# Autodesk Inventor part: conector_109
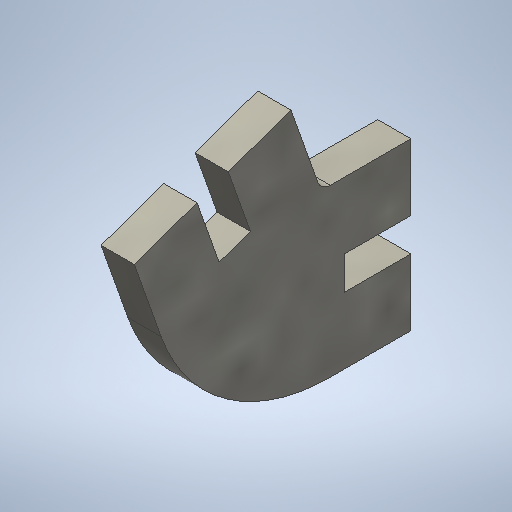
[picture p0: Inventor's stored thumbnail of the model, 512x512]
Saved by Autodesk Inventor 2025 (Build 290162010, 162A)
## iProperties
Created: 2025-02
Part Number: conector_109
Material: Paper
Document SubType Name: Modeling
Designer: BennF
Density: 0.93 g/cm^3
Appearance: Cardboard - Chipboard
Author: BennF
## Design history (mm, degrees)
sketch "Sketch2"
  geometry: L1 (0, -1)-(6.061, -1); L2 (6.061, -1)-(6.061, -6); L3 (6.061, -6)-(1.061, -6); L4 (1.061, -6)-(1.061, -8.5); L5 (1.061, -8.5)-(6.061, -8.5); L6 (6.061, -8.5)-(6.061, -13.5); L7 (6.061, -13.5)-(0, -13.5); L8 (-0.943, -0.333)-(-2.963, 5.381); L9 (-2.963, 5.381)-(-7.677, 3.714); L10 (-7.677, 3.714)-(-6.01, -1); L11 (-6.01, -1)-(-8.367, -1.833); L12 (-8.367, -1.833)-(-10.034, 2.881); L13 (-10.034, 2.881)-(-14.748, 1.214); L14 (-14.748, 1.214)-(-12.728, -4.5); L15 (-6.01, -1)-(1.061, -6); A1 r 1 centre (0, 0) between (-0.943, -0.333) and (0, -1); A2 r 13.5 centre (0, 0) between (-12.728, -4.5) and (0, -13.5); 1 further point
  constraints: 30 end point, 10 perpendicular, 5 equal length, 4 point on circle, 4 point on line, 4 tangent, 2 centre point, 2 coincident, 1 horizontal
  dimensions: "d0" = 2.5 distance of L3.end L4.end (= thickness); "d1" = 5 distance of L2.end L3.end (= slot_depth); "d2" = 5 distance of L1.end L2.end (= slot_dis_1); "d3" = 1 radius of A1; "d4" = 109.471 deg angle of L1 L8 (= con_angle_4); "d8" = 5 vertical distance of L3.end L10.end (computed from slot_clearenece)
extrude "Extrusion1" new body sketch "Sketch2" distance "d6" = 2.5 (= thickness); taper "d7" = 0 deg
sketch "laser"
  geometry: L1 (-3.714, -7.677)-(1, -6.01) reference; L2 (1, -6.01)-(1.833, -8.367) reference; L3 (1.833, -8.367)-(-2.881, -10.034) reference; L4 (-2.881, -10.034)-(-1.214, -14.748) reference; L5 (-1.214, -14.748)-(4.5, -12.728) reference; L6 (13.5, 0)-(13.5, 6.061) reference; L7 (13.5, 6.061)-(8.5, 6.061) reference; L8 (8.5, 6.061)-(8.5, 1.061) reference; L9 (8.5, 1.061)-(6, 1.061) reference; L10 (6, 1.061)-(6, 6.061) reference; L11 (6, 6.061)-(1, 6.061) reference; L12 (1, 6.061)-(1, 0) reference; L13 (0.333, -0.943)-(-5.381, -2.963) reference; L14 (-5.381, -2.963)-(-3.714, -7.677) reference; A1 r 13.5 centre (0, 0) between (4.5, -12.728) and (13.5, 0) reference; A2 r 1 centre (0, 0) between (0.333, -0.943) and (1, 0) reference; 1 further point
  node "Projected Loop1"
body "Solid1"
other parameters: "thickness" = 2.5 [user parameter; used in 2 equation terms], "clearence" = -0.5 [user parameter], "slot_depth" = 5 [user parameter; used in 1 equation term], "slot_dis_1" = 5 [user parameter; used in 1 equation term], "slot_dis_2" = 12 [user parameter], "slot_clearenece" = 3 [user parameter; used in 1 equation term], "con_angle_1" = 20.34444 [user parameter], "con_angle_2" = 60 deg [user parameter], "con_angle_3" = 12.30959 [user parameter], "con_angle_4" = 109.471 deg [user parameter; used in 1 equation term], "con_angle_5" = 24.11865 [user parameter]
